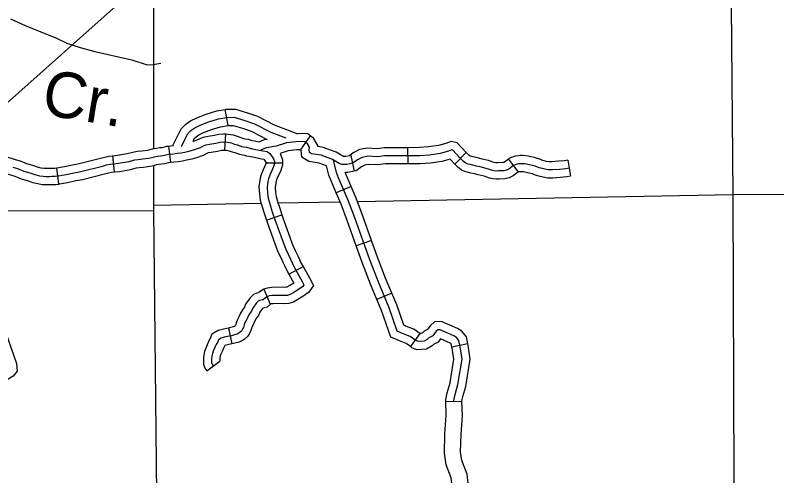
# Model space of a CAD drawing. Extents: x 1377389 to 1380723, y 1168351 to 1170484.
# Drawn here: x 1378871.6 to 1379012.3, y 1168888.3 to 1168973.5 of the extents above; entities that cross this region are included whole.
import ezdxf

# ---------------------------------------------------------------- set-up
doc = ezdxf.new("R2010")
doc.units = 0
doc.layers.add('B_Contour_Elevations', color=7, linetype='Continuous')
doc.layers.add('B_Fill', color=7, linetype='Continuous')

msp = doc.modelspace()

# ---------------------------------------------------------------- linework, layer by layer
at = {"layer": 'B_Contour_Elevations'}
msp.add_line((1378478.5, 1168608.3), (1379068.4, 1169134.14), dxfattribs=at)
at = {"layer": 'B_Fill'}
for p, q in [((1378910.92, 1168953.16), (1378910.41, 1168956.12)), ((1378910.32, 1168948.58), (1378910.5, 1168951.58)), ((1378926.12, 1168951.24), (1378924.4, 1168948.78)), ((1378900.34, 1168946.36), (1378899.97, 1168949.34)), ((1378944.1, 1168949.03), (1378944.13, 1168946.03)), ((1378889.92, 1168944.57), (1378889.62, 1168947.55)), ((1378933.59, 1168947.61), (1378934.23, 1168944.68)), ((1378954.91, 1168948.15), (1378952.84, 1168945.97)), ((1378962.73, 1168946.92), (1378964.5, 1168944.5)), ((1378918.01, 1168946.25), (1378921.01, 1168946.25)), ((1378973.68, 1168946.71), (1378974.2, 1168943.76)), ((1378879.64, 1168942.31), (1378879.29, 1168945.29)), ((1378933.67, 1168941.85), (1378930.92, 1168940.66)), ((1378918.04, 1168935.63), (1378920.88, 1168936.6)), ((1378937.45, 1168931.88), (1378934.62, 1168930.88)), ((1378922.14, 1168925.63), (1378924.77, 1168927.09)), ((1378917.55, 1168922.84), (1378918.69, 1168920.07)), ((1378941.21, 1168922.1), (1378938.44, 1168920.95)), ((1378911.01, 1168915.68), (1378911.61, 1168912.74)), ((1378946.36, 1168914.66), (1378944.61, 1168912.23)), ((1378955.23, 1168912.73), (1378952.29, 1168912.13)), ((1378954.16, 1168902.11), (1378951.16, 1168902.01))]:
    msp.add_line(p, q, dxfattribs=at)
for points in [[(1379004.27, 1168940.35), (1379003.36, 1169045.45)], [(1378897.14, 1169015.82), (1378897.15, 1168948.86)], [(1378870.74, 1168972.89), (1378873.45, 1168971.66), (1378879.25, 1168969.29), (1378881.13, 1168968.39), (1378883.59, 1168967.59), (1378886.29, 1168966.85), (1378893.12, 1168965.3), (1378895.82, 1168964.4), (1378896.72, 1168964.35), (1378898.48, 1168964.66)], [(1378900.72, 1168949.43), (1378902.27, 1168952.51), (1378903.09, 1168953.37), (1378904, 1168953.99), (1378905.18, 1168954.58), (1378906.87, 1168955.25), (1378908.82, 1168955.85), (1378910.41, 1168956.12)], [(1378910.42, 1168956.12), (1378910.53, 1168956.14), (1378912.28, 1168956.19), (1378914.52, 1168955.48), (1378916.37, 1168954.84), (1378919.42, 1168953.27), (1378921.06, 1168952.65)], [(1378903.51, 1168951.64), (1378904.06, 1168952.22), (1378904.76, 1168952.7), (1378905.79, 1168953.21), (1378907.37, 1168953.83), (1378909.17, 1168954.39), (1378910.67, 1168954.64), (1378912.06, 1168954.68), (1378914.05, 1168954.06), (1378915.78, 1168953.46)], [(1378904.45, 1168950.17), (1378904.75, 1168950.77), (1378905.04, 1168951.07), (1378905.52, 1168951.4), (1378906.4, 1168951.84), (1378907.86, 1168952.42), (1378909.51, 1168952.92), (1378910.92, 1168953.16)], [(1378910.81, 1168953.15), (1378911.85, 1168953.17), (1378913.58, 1168952.63), (1378915.18, 1168952.07), (1378918.12, 1168950.56)], [(1378915.78, 1168953.46), (1378918.81, 1168951.89), (1378921.61, 1168950.84)], [(1378921.06, 1168952.65), (1378923.8, 1168951.62)], [(1378902.31, 1168949.26), (1378903.51, 1168951.64)], [(1378904.56, 1168950.22), (1378905.24, 1168950.46), (1378905.65, 1168950.65), (1378906.34, 1168950.99), (1378907.27, 1168951.17), (1378908.4, 1168951.34), (1378909.23, 1168951.54), (1378910.05, 1168951.6), (1378910.5, 1168951.58)], [(1378910.5, 1168951.58), (1378910.99, 1168951.55), (1378911.85, 1168951.4), (1378912.61, 1168951.14), (1378913.12, 1168950.97), (1378913.77, 1168950.74), (1378914.04, 1168950.69), (1378914.67, 1168950.61), (1378915.14, 1168950.45), (1378915.76, 1168950.31), (1378916.71, 1168950.12)], [(1378926.12, 1168951.24), (1378925.66, 1168951.57), (1378924.63, 1168951.66), (1378923.8, 1168951.62)], [(1378933.34, 1168947.56), (1378932.71, 1168947.42), (1378932.23, 1168947.42), (1378932.1, 1168947.47), (1378930.87, 1168948.23), (1378928.5, 1168949.09), (1378927.5, 1168949.25), (1378927.52, 1168949.44), (1378926.73, 1168950.81), (1378926.12, 1168951.24)], [(1378900.81, 1168947.93), (1378901.54, 1168948), (1378902.27, 1168948.11), (1378902.96, 1168948.23), (1378903.9, 1168948.45), (1378904.72, 1168948.68), (1378905.81, 1168949.07), (1378906.29, 1168949.3), (1378906.82, 1168949.55), (1378907.52, 1168949.69), (1378908.69, 1168949.87), (1378909.47, 1168950.05), (1378910.06, 1168950.1), (1378910.81, 1168950.05), (1378911.47, 1168949.94), (1378912.14, 1168949.71), (1378912.64, 1168949.55), (1378913.39, 1168949.28), (1378913.82, 1168949.21), (1378914.33, 1168949.14), (1378914.74, 1168949), (1378915.45, 1168948.84), (1378916.7, 1168948.59), (1378917.36, 1168948.43), (1378918.16, 1168948.36), (1378918.62, 1168947.97), (1378919.33, 1168946.97), (1378919.51, 1168946.49), (1378919.51, 1168946.1), (1378919.26, 1168945.39), (1378918.62, 1168943.95), (1378918.39, 1168943.29), (1378918.28, 1168942.77), (1378918.12, 1168941.74), (1378918.21, 1168940.6), (1378918.34, 1168939.68), (1378918.69, 1168938.49), (1378919.03, 1168937.37), (1378919.65, 1168935.57), (1378921.52, 1168930.36), (1378922, 1168929.36), (1378922.48, 1168928.4), (1378922.77, 1168927.73), (1378923.05, 1168927.09), (1378924.62, 1168924.26), (1378924.94, 1168923.64), (1378924.76, 1168923.37), (1378923.94, 1168922.78), (1378923.07, 1168922.27), (1378922.38, 1168921.86), (1378921.91, 1168921.72), (1378921.15, 1168921.68), (1378920.03, 1168921.72), (1378919.14, 1168921.68), (1378918.5, 1168921.61), (1378918.12, 1168921.45), (1378917.87, 1168921.29), (1378917.43, 1168920.92), (1378917.23, 1168920.88), (1378916.75, 1168920.74), (1378916.5, 1168920.63), (1378916.15, 1168920.31), (1378915.49, 1168919.35), (1378915.26, 1168918.82), (1378914.85, 1168918.23), (1378914.56, 1168917.7), (1378914.19, 1168916.95), (1378914.05, 1168916.68), (1378913.92, 1168916.26), (1378913.76, 1168915.78), (1378913.55, 1168915.35), (1378913.41, 1168915.12), (1378913, 1168914.76), (1378912.68, 1168914.57), (1378912.32, 1168914.46), (1378911.54, 1168914.25), (1378910.42, 1168914.03), (1378909.65, 1168913.8), (1378909.15, 1168913.52), (1378909.01, 1168913.13), (1378908.71, 1168912.63), (1378908.44, 1168911.95), (1378908.19, 1168911.4), (1378908.03, 1168910.94), (1378907.94, 1168910.46), (1378907.89, 1168909.98), (1378907.87, 1168909.61), (1378907.89, 1168909.24), (1378907.97, 1168908.98), (1378908.2, 1168908.68)], [(1378918.12, 1168950.56), (1378917.62, 1168950.48), (1378916.71, 1168950.12)], [(1378973.94, 1168945.23), (1378973.31, 1168945.12), (1378972.18, 1168945.03), (1378970.89, 1168944.93), (1378970.13, 1168944.93), (1378969.47, 1168945.05), (1378968.72, 1168945.23), (1378968.39, 1168945.33), (1378968.09, 1168945.44), (1378967.64, 1168945.63), (1378967.21, 1168945.74), (1378966.57, 1168945.87), (1378966.07, 1168945.98), (1378965.73, 1168946.06), (1378965.36, 1168946.07), (1378964.98, 1168946.07), (1378964.66, 1168946.06), (1378964.35, 1168946.02), (1378963.95, 1168945.89), (1378963.65, 1168945.74), (1378963.17, 1168945.38), (1378962.79, 1168945.08), (1378962.38, 1168944.88), (1378961.88, 1168944.78), (1378960.92, 1168944.73), (1378960.53, 1168944.71), (1378960.12, 1168944.76), (1378959.63, 1168944.88), (1378959.24, 1168945.01), (1378958.64, 1168945.21), (1378957.52, 1168945.47), (1378956.86, 1168945.64), (1378956.15, 1168945.81), (1378955.68, 1168945.92), (1378955.27, 1168946), (1378955.05, 1168946.07), (1378954.85, 1168946.18), (1378954.63, 1168946.35), (1378954.39, 1168946.56), (1378954.14, 1168946.81), (1378953.77, 1168947.16), (1378952.45, 1168948.59), (1378952.26, 1168948.64), (1378951.65, 1168948.4), (1378950.12, 1168947.98), (1378948.15, 1168947.67), (1378946.36, 1168947.56), (1378944.03, 1168947.53), (1378941.41, 1168947.53), (1378939.86, 1168947.54), (1378938.53, 1168947.35), (1378936.77, 1168947.44), (1378935.72, 1168947.25), (1378934.82, 1168946.78), (1378933.96, 1168946.16), (1378932.87, 1168945.92), (1378931.97, 1168945.92), (1378931.44, 1168946.11), (1378930.21, 1168946.87), (1378928.12, 1168947.63), (1378926.36, 1168947.92), (1378925.98, 1168948.16), (1378925.93, 1168948.63), (1378925.98, 1168949.11), (1378925.6, 1168949.78), (1378925.12, 1168950.11), (1378924.6, 1168950.16), (1378923.5, 1168950.11), (1378921.7, 1168949.92), (1378919.84, 1168949.3), (1378918.01, 1168949.03), (1378916.94, 1168948.6)], [(1378954.91, 1168948.15), (1378954.84, 1168948.21), (1378953.25, 1168949.94), (1378952.17, 1168950.21), (1378951.18, 1168949.83), (1378949.81, 1168949.45), (1378947.98, 1168949.17), (1378946.3, 1168949.06), (1378944.1, 1168949.03)], [(1378889.62, 1168947.55), (1378890.47, 1168947.63), (1378892.26, 1168947.96), (1378893.35, 1168948.23), (1378894.12, 1168948.37), (1378894.98, 1168948.44), (1378896.01, 1168948.59), (1378896.54, 1168948.68), (1378896.97, 1168948.81), (1378897.62, 1168948.95), (1378898.31, 1168949.06), (1378898.73, 1168949.08), (1378899.63, 1168949.29), (1378899.97, 1168949.34)], [(1378899.97, 1168949.34), (1378900.65, 1168949.42), (1378900.83, 1168949.44)], [(1378900.34, 1168946.36), (1378900.98, 1168946.44), (1378901.73, 1168946.51), (1378902.51, 1168946.63), (1378903.26, 1168946.76), (1378904.27, 1168947), (1378905.17, 1168947.25), (1378906.39, 1168947.68), (1378906.94, 1168947.95), (1378907.29, 1168948.12), (1378907.78, 1168948.21), (1378908.98, 1168948.4), (1378909.7, 1168948.57), (1378910.07, 1168948.6), (1378910.32, 1168948.58)], [(1378910.32, 1168948.58), (1378910.64, 1168948.56), (1378911.1, 1168948.48), (1378911.66, 1168948.29), (1378912.15, 1168948.13), (1378913.01, 1168947.82), (1378913.61, 1168947.72), (1378913.99, 1168947.67), (1378914.33, 1168947.56), (1378915.13, 1168947.38), (1378916.38, 1168947.13), (1378917.12, 1168946.95), (1378917.53, 1168946.91), (1378917.99, 1168946.26), (1378918.01, 1168946.21), (1378918.01, 1168946.25)], [(1378924.42, 1168948.65), (1378923.62, 1168948.61), (1378922.02, 1168948.44), (1378920.56, 1168947.96)], [(1378929.13, 1168945.67), (1378927.74, 1168946.18), (1378925.82, 1168946.49), (1378924.56, 1168947.28), (1378924.42, 1168948.65)], [(1378944.1, 1168949.03), (1378944.02, 1168949.03), (1378941.42, 1168949.03), (1378939.76, 1168949.04), (1378938.46, 1168948.85), (1378936.67, 1168948.95), (1378935.23, 1168948.69), (1378934.03, 1168948.06), (1378933.34, 1168947.56)], [(1378869.64, 1168947.46), (1378869.84, 1168947.41), (1378871.58, 1168946.87), (1378872.53, 1168946.58), (1378873.69, 1168946.12), (1378874.76, 1168945.79), (1378875.63, 1168945.49), (1378876.33, 1168945.34), (1378876.89, 1168945.24), (1378877.35, 1168945.23), (1378877.84, 1168945.23), (1378878.41, 1168945.25), (1378878.91, 1168945.25), (1378879.29, 1168945.29)], [(1378871.14, 1168945.44), (1378872.03, 1168945.16), (1378873.19, 1168944.71), (1378874.29, 1168944.37), (1378875.23, 1168944.05), (1378876.05, 1168943.86), (1378876.73, 1168943.75), (1378877.33, 1168943.73), (1378877.87, 1168943.73), (1378878.44, 1168943.75), (1378878.99, 1168943.75), (1378879.59, 1168943.82), (1378880.25, 1168943.93), (1378880.98, 1168944.07), (1378882.48, 1168944.41), (1378883.72, 1168944.64), (1378887.71, 1168945.64), (1378888.49, 1168945.85), (1378889.13, 1168945.99), (1378889.74, 1168946.06), (1378890.68, 1168946.15), (1378892.57, 1168946.49), (1378893.67, 1168946.76), (1378894.31, 1168946.88), (1378895.15, 1168946.95), (1378896.25, 1168947.11), (1378896.89, 1168947.22), (1378897.34, 1168947.36), (1378897.89, 1168947.47), (1378898.46, 1168947.56), (1378898.94, 1168947.59), (1378899.9, 1168947.82), (1378900.81, 1168947.93)], [(1378879.29, 1168945.29), (1378879.37, 1168945.3), (1378879.98, 1168945.41), (1378880.67, 1168945.54), (1378882.18, 1168945.88), (1378883.4, 1168946.11), (1378887.34, 1168947.1), (1378888.14, 1168947.31), (1378888.89, 1168947.47), (1378889.59, 1168947.55), (1378889.62, 1168947.55)], [(1378920.56, 1168947.96), (1378921.01, 1168946.77), (1378921.01, 1168946.25)], [(1378952.66, 1168902.06), (1378952.65, 1168902.26), (1378952.86, 1168903.36), (1378953.41, 1168905.22), (1378954.16, 1168909.9), (1378953.81, 1168912.22), (1378953.56, 1168913.4), (1378953.14, 1168913.94), (1378952.66, 1168914.21), (1378950.13, 1168915.33), (1378949.68, 1168915.36), (1378949.38, 1168915.09), (1378949.05, 1168914.64), (1378948.75, 1168914.24), (1378948.02, 1168913.88), (1378947.69, 1168913.55), (1378947.15, 1168913.22), (1378946.07, 1168913.16), (1378945.63, 1168913.34), (1378944.55, 1168914.12), (1378943.16, 1168914.67), (1378942.2, 1168915.09), (1378940.69, 1168919.43), (1378938.65, 1168924.37), (1378937.14, 1168928.29), (1378934.37, 1168936.06), (1378933.2, 1168939.16), (1378932.28, 1168941.28), (1378931.34, 1168943.46), (1378930.96, 1168944.42), (1378930.42, 1168946.74)], [(1378952.84, 1168945.97), (1378952.7, 1168946.1), (1378951.94, 1168946.93), (1378950.44, 1168946.51), (1378948.31, 1168946.18), (1378946.41, 1168946.06), (1378944.13, 1168946.03)], [(1378962.73, 1168946.92), (1378962.26, 1168946.57), (1378961.98, 1168946.35), (1378961.9, 1168946.31), (1378961.7, 1168946.28), (1378960.84, 1168946.23), (1378960.6, 1168946.21), (1378960.39, 1168946.24), (1378960.04, 1168946.32), (1378959.72, 1168946.43), (1378959.05, 1168946.66), (1378957.88, 1168946.92), (1378957.23, 1168947.1), (1378956.48, 1168947.28), (1378955.99, 1168947.38), (1378955.66, 1168947.45), (1378955.65, 1168947.45), (1378955.59, 1168947.5), (1378955.41, 1168947.66), (1378955.18, 1168947.89), (1378954.91, 1168948.15)], [(1378973.68, 1168946.71), (1378973.11, 1168946.61), (1378972.07, 1168946.52), (1378970.84, 1168946.43), (1378970.25, 1168946.43), (1378969.78, 1168946.51), (1378969.11, 1168946.68), (1378968.85, 1168946.75), (1378968.64, 1168946.83), (1378968.12, 1168947.05), (1378967.55, 1168947.2), (1378966.89, 1168947.34), (1378966.39, 1168947.45), (1378965.93, 1168947.55), (1378965.39, 1168947.57), (1378964.94, 1168947.57), (1378964.53, 1168947.55), (1378964.02, 1168947.49), (1378963.38, 1168947.28), (1378962.87, 1168947.02), (1378962.73, 1168946.92)], [(1378889.92, 1168944.57), (1378890.89, 1168944.66), (1378892.89, 1168945.02), (1378893.98, 1168945.3), (1378894.5, 1168945.39), (1378895.32, 1168945.46), (1378896.49, 1168945.63), (1378897.24, 1168945.76), (1378897.71, 1168945.9), (1378898.16, 1168946), (1378898.62, 1168946.07), (1378899.15, 1168946.09), (1378900.17, 1168946.34), (1378900.34, 1168946.36)], [(1378897.15, 1168945.59), (1378897.15, 1168938.38), (1378897.14, 1168937.4), (1378898.24, 1168832.29), (1378898.26, 1168831.5), (1378898.43, 1168809.84)], [(1378918.01, 1168946.36), (1378917.86, 1168945.95), (1378917.22, 1168944.5), (1378916.94, 1168943.7), (1378916.8, 1168943.04), (1378916.61, 1168941.79), (1378916.72, 1168940.42), (1378916.88, 1168939.36), (1378917.25, 1168938.07), (1378917.6, 1168936.91), (1378918.04, 1168935.63)], [(1378921.01, 1168946.25), (1378921.01, 1168945.84), (1378920.65, 1168944.84), (1378920.02, 1168943.4), (1378919.84, 1168942.89), (1378919.75, 1168942.49), (1378919.63, 1168941.68), (1378919.7, 1168940.77), (1378919.81, 1168940), (1378920.12, 1168938.92), (1378920.46, 1168937.84), (1378920.88, 1168936.6)], [(1378930.92, 1168940.66), (1378930.9, 1168940.69), (1378929.95, 1168942.88), (1378929.52, 1168943.97), (1378929.13, 1168945.67)], [(1378944.13, 1168946.03), (1378944.03, 1168946.03), (1378941.41, 1168946.03), (1378939.96, 1168946.04), (1378938.6, 1168945.84), (1378936.86, 1168945.94), (1378936.22, 1168945.82), (1378935.61, 1168945.5), (1378934.59, 1168944.76), (1378934.23, 1168944.68)], [(1378964.5, 1168944.5), (1378964.08, 1168944.19), (1378963.61, 1168943.81), (1378962.86, 1168943.44), (1378962.06, 1168943.29), (1378961, 1168943.23), (1378960.46, 1168943.2), (1378959.85, 1168943.29), (1378959.23, 1168943.43), (1378958.76, 1168943.59), (1378958.23, 1168943.77), (1378957.16, 1168944.01), (1378956.49, 1168944.19), (1378955.81, 1168944.35), (1378955.37, 1168944.45), (1378954.88, 1168944.55), (1378954.46, 1168944.69), (1378954.03, 1168944.91), (1378953.67, 1168945.19), (1378953.37, 1168945.46), (1378953.1, 1168945.72), (1378952.84, 1168945.97)], [(1378868.87, 1168944.56), (1378869.02, 1168944.52), (1378870.7, 1168944.01), (1378871.53, 1168943.75), (1378872.7, 1168943.29), (1378873.82, 1168942.94), (1378874.82, 1168942.6), (1378875.76, 1168942.39), (1378876.58, 1168942.25), (1378877.3, 1168942.23), (1378877.9, 1168942.23), (1378878.47, 1168942.25), (1378879.08, 1168942.25), (1378879.64, 1168942.31)], [(1378879.64, 1168942.31), (1378879.8, 1168942.33), (1378880.51, 1168942.45), (1378881.28, 1168942.6), (1378882.79, 1168942.94), (1378884.04, 1168943.17), (1378888.09, 1168944.19), (1378888.84, 1168944.39), (1378889.37, 1168944.5), (1378889.9, 1168944.56), (1378889.92, 1168944.57)], [(1378934.23, 1168944.68), (1378933.03, 1168944.42), (1378932.57, 1168944.42)], [(1378933.67, 1168941.85), (1378933.66, 1168941.88), (1378932.73, 1168944.03), (1378932.57, 1168944.42)], [(1378974.2, 1168943.76), (1378973.5, 1168943.63), (1378972.3, 1168943.53), (1378970.95, 1168943.43), (1378970, 1168943.43), (1378969.16, 1168943.58), (1378968.34, 1168943.78), (1378967.92, 1168943.9), (1378967.53, 1168944.04), (1378967.16, 1168944.2), (1378966.87, 1168944.28), (1378966.26, 1168944.4), (1378965.74, 1168944.52), (1378965.53, 1168944.56), (1378965.32, 1168944.57), (1378965.03, 1168944.57), (1378964.8, 1168944.56), (1378964.67, 1168944.55), (1378964.53, 1168944.5), (1378964.44, 1168944.45), (1378964.5, 1168944.5)], [(1378937.45, 1168931.88), (1378935.78, 1168936.58), (1378934.59, 1168939.72), (1378933.67, 1168941.85)], [(1378934.62, 1168930.88), (1378932.96, 1168935.55), (1378931.81, 1168938.59), (1378930.92, 1168940.66)], [(1378934.83, 1168939.08), (1379004.27, 1168940.35)], [(1379004.27, 1168940.35), (1379110.34, 1168940.86)], [(1379004.6, 1168834.23), (1379004.27, 1168940.35)], [(1378897.15, 1168938.38), (1378917.09, 1168938.75)], [(1378920.2, 1168938.81), (1378931.56, 1168939.02)], [(1378869.6, 1168937.33), (1378897.14, 1168937.4)], [(1378918.04, 1168935.63), (1378918.23, 1168935.07), (1378920.13, 1168929.78), (1378920.65, 1168928.7), (1378921.12, 1168927.75), (1378921.4, 1168927.13), (1378921.7, 1168926.43), (1378922.14, 1168925.63)], [(1378920.88, 1168936.6), (1378921.06, 1168936.07), (1378922.9, 1168930.94), (1378923.34, 1168930.01), (1378923.83, 1168929.04), (1378924.15, 1168928.33), (1378924.4, 1168927.75), (1378924.77, 1168927.09)], [(1378941.21, 1168922.1), (1378940.04, 1168924.93), (1378938.55, 1168928.81), (1378937.45, 1168931.88)], [(1378938.44, 1168920.95), (1378937.25, 1168923.81), (1378935.73, 1168927.77), (1378934.62, 1168930.88)], [(1378924.77, 1168927.09), (1378925.94, 1168924.97), (1378926.68, 1168923.55), (1378925.86, 1168922.31), (1378924.75, 1168921.52), (1378923.83, 1168920.98), (1378922.99, 1168920.47), (1378922.16, 1168920.24), (1378921.17, 1168920.18), (1378920.04, 1168920.22), (1378919.26, 1168920.18), (1378918.88, 1168920.14), (1378918.69, 1168920.07)], [(1378922.14, 1168925.63), (1378923.05, 1168924), (1378922.31, 1168923.56), (1378921.78, 1168923.25), (1378921.65, 1168923.21), (1378921.14, 1168923.18), (1378920.03, 1168923.23), (1378919.02, 1168923.17), (1378918.13, 1168923.08), (1378917.55, 1168922.84)], [(1378917.55, 1168922.84), (1378917.42, 1168922.79), (1378916.97, 1168922.5), (1378916.73, 1168922.3), (1378916.23, 1168922.15), (1378915.65, 1168921.89), (1378915.01, 1168921.29), (1378914.17, 1168920.08), (1378913.95, 1168919.56), (1378913.58, 1168919.03), (1378913.23, 1168918.4), (1378912.84, 1168917.61), (1378912.66, 1168917.25), (1378912.49, 1168916.74), (1378912.36, 1168916.34), (1378912.24, 1168916.08), (1378912.12, 1168915.98), (1378912.08, 1168915.96), (1378911.9, 1168915.9), (1378911.2, 1168915.71), (1378911.01, 1168915.68)], [(1378946.36, 1168914.66), (1378945.27, 1168915.45), (1378943.74, 1168916.05), (1378943.4, 1168916.2), (1378942.1, 1168919.96), (1378941.21, 1168922.1)], [(1378918.81, 1168920.11), (1378918.76, 1168920.08), (1378918.12, 1168919.54), (1378917.6, 1168919.42), (1378917.32, 1168919.35), (1378917.3, 1168919.32), (1378916.81, 1168918.62), (1378916.58, 1168918.09), (1378916.12, 1168917.43), (1378915.88, 1168917.01), (1378915.54, 1168916.29), (1378915.44, 1168916.1), (1378915.34, 1168915.79), (1378915.15, 1168915.22), (1378914.88, 1168914.64), (1378914.58, 1168914.15), (1378913.88, 1168913.53), (1378913.29, 1168913.19), (1378912.73, 1168913.02), (1378911.88, 1168912.79), (1378911.61, 1168912.74)], [(1378944.61, 1168912.23), (1378943.82, 1168912.8), (1378942.59, 1168913.28), (1378941, 1168913.98), (1378939.29, 1168918.89), (1378938.44, 1168920.95)], [(1378869.33, 1168916.39), (1378871.81, 1168909.13), (1378871.96, 1168907.7), (1378871.19, 1168906.8), (1378870.1, 1168906.09), (1378868.79, 1168905.79), (1378868.73, 1168905.78)], [(1378955.23, 1168912.73), (1378954.96, 1168914.04), (1378954.14, 1168915.1), (1378953.33, 1168915.56), (1378950.5, 1168916.81), (1378949.15, 1168916.9), (1378948.26, 1168916.1), (1378947.85, 1168915.54), (1378947.77, 1168915.43), (1378947.14, 1168915.11), (1378946.76, 1168914.74), (1378946.69, 1168914.7), (1378946.34, 1168914.68), (1378946.36, 1168914.66)], [(1378911.01, 1168915.68), (1378910.06, 1168915.48), (1378909.07, 1168915.19), (1378907.92, 1168914.56), (1378907.64, 1168913.77), (1378907.36, 1168913.3), (1378907.06, 1168912.54), (1378906.79, 1168911.96), (1378906.57, 1168911.33), (1378906.45, 1168910.67), (1378906.39, 1168910.08), (1378906.37, 1168909.62), (1378906.39, 1168908.98), (1378906.63, 1168908.28), (1378906.99, 1168907.78), (1378909.4, 1168909.57)], [(1378952.29, 1168912.13), (1378952.17, 1168912.76), (1378952.14, 1168912.78), (1378951.99, 1168912.87), (1378950.19, 1168913.66), (1378949.73, 1168913.06), (1378948.91, 1168912.65), (1378948.63, 1168912.36), (1378947.61, 1168911.74), (1378945.81, 1168911.64), (1378944.89, 1168912.02), (1378944.61, 1168912.23)], [(1378911.61, 1168912.74), (1378910.79, 1168912.57), (1378910.34, 1168912.44), (1378910.06, 1168911.97), (1378909.82, 1168911.36), (1378909.58, 1168910.84), (1378909.48, 1168910.55), (1378909.42, 1168910.25), (1378909.39, 1168909.88), (1378909.38, 1168909.6), (1378909.4, 1168909.57)], [(1378951.16, 1168902.01), (1378951.15, 1168902.37), (1378951.4, 1168903.71), (1378951.94, 1168905.55), (1378952.64, 1168909.9), (1378952.33, 1168911.96), (1378952.29, 1168912.13)], [(1378954.16, 1168902.11), (1378954.15, 1168902.15), (1378954.32, 1168903.01), (1378954.87, 1168904.88), (1378955.68, 1168909.89), (1378955.28, 1168912.49), (1378955.23, 1168912.73)], [(1378952.23, 1168872.78), (1378952.03, 1168874.49), (1378951.94, 1168876.57), (1378951.94, 1168878.21), (1378951.89, 1168879.09), (1378951.95, 1168880.36), (1378952.18, 1168881.82), (1378952.36, 1168883.05), (1378952.39, 1168884.5), (1378952.34, 1168886.3), (1378952.17, 1168887.96), (1378951.24, 1168890.36), (1378950.89, 1168892.52), (1378950.98, 1168896.13), (1378951.22, 1168899.54), (1378951.16, 1168902.02)], [(1378955.1, 1168871.92), (1378955.03, 1168874.65), (1378954.94, 1168876.63), (1378954.94, 1168878.31), (1378954.89, 1168879.11), (1378954.94, 1168880.05), (1378955.15, 1168881.37), (1378955.36, 1168882.81), (1378955.39, 1168884.52), (1378955.33, 1168886.5), (1378955.11, 1168888.67), (1378954.15, 1168891.15), (1378953.89, 1168892.72), (1378953.97, 1168895.99), (1378954.22, 1168899.47), (1378954.15, 1168902.15)]]:
    msp.add_lwpolyline(points, dxfattribs=at)

# ---------------------------------------------------------------- texts
msp.add_text('Cr.', height=8.448, rotation=350.6893, dxfattribs=at).set_placement((1378876.22, 1168955.26))

doc.saveas('drawing.dxf')
